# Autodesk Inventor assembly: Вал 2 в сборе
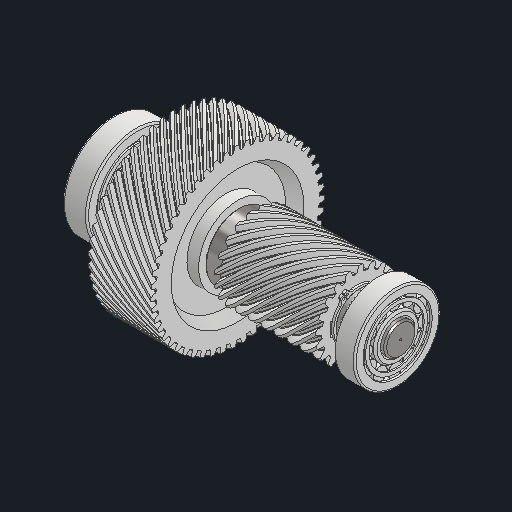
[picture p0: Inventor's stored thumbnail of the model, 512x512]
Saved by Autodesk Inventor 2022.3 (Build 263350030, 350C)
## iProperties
Created: 2022-08
Part Number: Вал 2 в сборе
Document SubType Name: Assembly
Designer: Карташов
Author: Карташов
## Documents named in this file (10)
- C:\Users\wsr\Desktop\Новая папка\10. Редуктор\Вал 2 в сборе.iam
- C:\Users\wsr\Desktop\Новая папка\10. Редуктор\Вал 2.ipt
- C:\Users\wsr\Desktop\Новая папка\10. Редуктор\GIVEN\ISO 15 - 40 x 110 x 27.ipt
- C:\Users\wsr\Desktop\Новая папка\10. Редуктор\GIVEN\ISO 15 - 50 x 130 x 31.ipt
- C:\Users\wsr\Desktop\Новая папка\10. Редуктор\GIVEN\Стопорное кольцо DIN 471 - 60 x 3.ipt
- C:\Users\wsr\Desktop\Новая папка\10. Редуктор\GIVEN\Стопорное кольцр DIN 471 - 70 x 4.ipt
- C:\Users\wsr\Desktop\Новая папка\10. Редуктор\GIVEN\Червяк 2.ipt
- C:\Users\wsr\Desktop\Новая папка\10. Редуктор\GIVEN\Шестерня 1.ipt
- C:\Users\wsr\Desktop\Новая папка\10. Редуктор\GIVEN\Шпонка ISO 2491 18x7-70-A.ipt
- C:\Users\wsr\Desktop\Новая папка\10. Редуктор\GIVEN\Шпонка ISO 2491 20x8-63-A.ipt
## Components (9 placed, 9 different names)
1. Вал 2:1 — С поворотом:1, С поворотом:2, Совмещение:1, Совмещение:2, Совмещение:3, Совмещение:4, Совмещение:6, Совмещение:7, Совмещение:8, Совмещение:9, Совмещение:10, Совмещение:12, С поворотом:4
2. ISO 15 - 40 x 110 x 27:1 — С поворотом:2
3. ISO 15 - 50 x 130 x 31:1 — С поворотом:1
4. Стопорное кольцо DIN 471 - 60 x 3:1 — С поворотом:4
5. Стопорное кольцр DIN 471 - 70 x 4:1 — С поворотом:3
6. Червяк 2:1 — Совмещение:4, Совмещение:5, Совмещение:6
7. Шестерня 1:1 — Совмещение:10, Совмещение:11, Совмещение:12, С поворотом:3
8. Шпонка ISO 2491 18x7-70-A:1 — Совмещение:1, Совмещение:2, Совмещение:3, Совмещение:5
9. Шпонка ISO 2491 20x8-63-A:1 — Совмещение:7, Совмещение:8, Совмещение:9, Совмещение:11
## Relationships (16: Mate 12, RevoluteJoint 4)
- С поворотом:1 [RevoluteJoint]: Вал 2:1 ↔ ISO 15 - 50 x 130 x 31:1
- С поворотом:2 [RevoluteJoint]: Вал 2:1 ↔ ISO 15 - 40 x 110 x 27:1
- Совмещение:1 [Mate]: Вал 2:1 ↔ Шпонка ISO 2491 18x7-70-A:1
- Совмещение:2 [Mate]: Вал 2:1 ↔ Шпонка ISO 2491 18x7-70-A:1
- Совмещение:3 [Mate]: Вал 2:1 ↔ Шпонка ISO 2491 18x7-70-A:1
- Совмещение:4 [Mate]: Вал 2:1 ↔ Червяк 2:1
- Совмещение:5 [Mate]: Червяк 2:1 ↔ Шпонка ISO 2491 18x7-70-A:1
- Совмещение:6 [Mate]: Вал 2:1 ↔ Червяк 2:1
- Совмещение:7 [Mate]: Вал 2:1 ↔ Шпонка ISO 2491 20x8-63-A:1
- Совмещение:8 [Mate]: Вал 2:1 ↔ Шпонка ISO 2491 20x8-63-A:1
- Совмещение:9 [Mate]: Вал 2:1 ↔ Шпонка ISO 2491 20x8-63-A:1
- Совмещение:10 [Mate]: Вал 2:1 ↔ Шестерня 1:1
- Совмещение:11 [Mate]: Шестерня 1:1 ↔ Шпонка ISO 2491 20x8-63-A:1
- Совмещение:12 [Mate]: Вал 2:1 ↔ Шестерня 1:1
- С поворотом:3 [RevoluteJoint]: Стопорное кольцр DIN 471 - 70 x 4:1 ↔ Шестерня 1:1
- С поворотом:4 [RevoluteJoint]: Вал 2:1 ↔ Стопорное кольцо DIN 471 - 60 x 3:1
